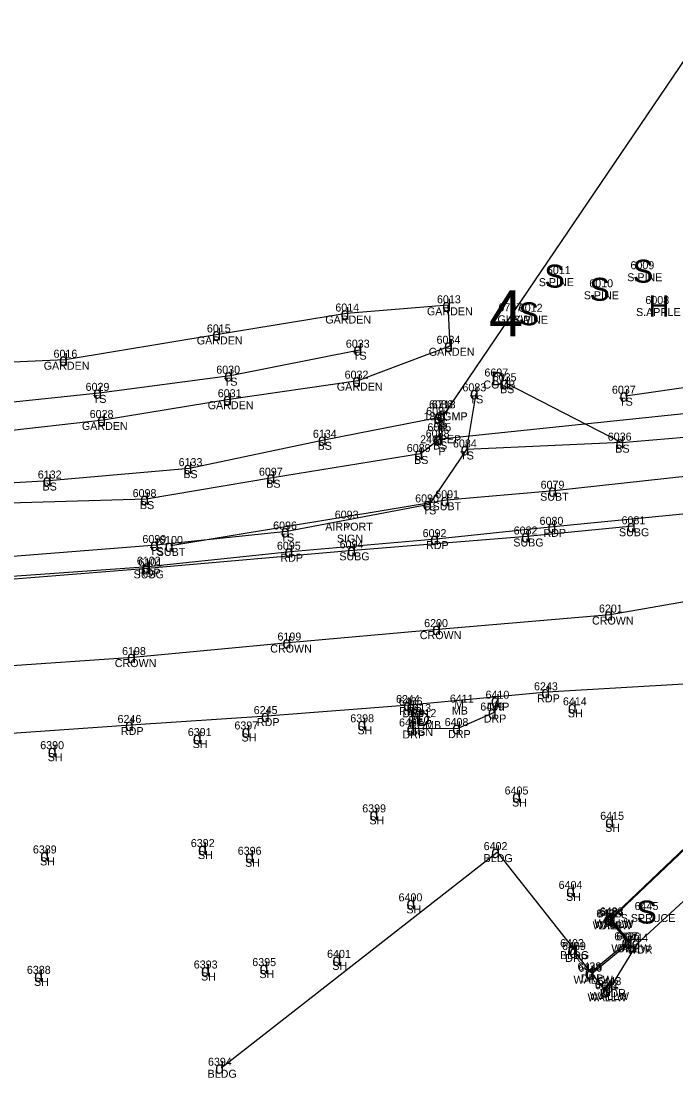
# Model space of a CAD drawing. Extents: x 69415 to 80913, y 7576 to 15059.
# Drawn here: x 75428.5 to 75592.2, y 14328.5 to 14592.6 of the extents above; entities that cross this region are included whole.
import ezdxf

# ---------------------------------------------------------------- set-up
doc = ezdxf.new("R2010")
doc.units = 0
for name, color, linetype in [('Level 11', 7, 'Continuous'), ('Level 12', 7, 'Continuous'), ('Level 13', 7, 'Continuous'), ('Level 14', 7, 'Continuous'), ('Level 15', 7, 'Continuous'), ('Level 43', 7, 'Continuous'), ('Level 46', 7, 'Continuous'), ('Level 47', 7, 'Continuous'), ('Level 48', 7, 'Continuous'), ('Level 59', 7, 'Continuous')]:
    doc.layers.add(name, color=color, linetype=linetype)

msp = doc.modelspace()

# ---------------------------------------------------------------- linework, layer by layer
at = {"layer": 'Level 11'}
for p, q in [((75607, 14470.73), (75561.56, 14466.24)), ((75561.56, 14466.24), (75532.22, 14463.17)), ((75532.22, 14463.17), (75495.79, 14460.02)), ((75495.79, 14460.02), (75460.21, 14456.27)), ((75460.21, 14456.27), (75423.86, 14453.65)), ((75595.57, 14427.04), (75560, 14424.88)), ((75560, 14424.88), (75525.49, 14421.7)), ((75525.49, 14421.7), (75489.92, 14418.94)), ((75546.65, 14419.82), (75547.4, 14422.78)), ((75489.92, 14418.94), (75455.92, 14416.71)), ((75526.32, 14421.13), (75526.33, 14415.84)), ((75537.73, 14415.94), (75546.65, 14419.82)), ((75455.92, 14416.71), (75417.43, 14413.97)), ((75526.33, 14415.84), (75537.73, 14415.94)), ((75598.04, 14389.54), (75575.57, 14368.11)), ((75575.57, 14368.11), (75580.07, 14362.41)), ((75580.07, 14362.41), (75570.88, 14354.86)), ((75570.88, 14354.86), (75567.01, 14359.97))]:
    msp.add_line(p, q, dxfattribs=at)
at = {"layer": 'Level 12'}
for p, q in [((75509.84, 14519.56), (75477.71, 14514.33)), ((75535.25, 14521.61), (75509.84, 14519.56)), ((75535.7, 14511.5), (75535.25, 14521.61)), ((75477.71, 14514.33), (75439.43, 14508.01)), ((75512.72, 14502.78), (75535.7, 14511.5)), ((75439.43, 14508.01), (75404.38, 14506.4)), ((75480.44, 14498.14), (75512.72, 14502.78)), ((75448.98, 14492.95), (75480.44, 14498.14)), ((75416.33, 14489.34), (75448.98, 14492.95)), ((75598.04, 14389.21), (75576.43, 14368.63)), ((75576.43, 14368.63), (75576.38, 14368.47)), ((75576.38, 14368.47), (75575.94, 14368.13)), ((75575.94, 14368.13), (75580.61, 14362.37)), ((75580.61, 14362.37), (75571.16, 14354.53)), ((75571.16, 14354.53), (75574.66, 14350.17)), ((75574.66, 14350.17), (75575.22, 14350.51))]:
    msp.add_line(p, q, dxfattribs=at)
at = {"layer": 'Level 13'}
for p, q in [((75478.48, 14331.04), (75547.49, 14384.94)), ((75547.49, 14384.94), (75566.61, 14360.69))]:
    msp.add_line(p, q, dxfattribs=at)
at = {"layer": 'Level 14'}
for p, q in [((75582.58, 14362.06), (75599.04, 14377.27)), ((75575.87, 14351.2), (75582.58, 14362.06))]:
    msp.add_line(p, q, dxfattribs=at)
at = {"layer": 'Level 15'}
for p, q in [((75595.97, 14478.96), (75561.74, 14475.27)), ((75561.74, 14475.27), (75534.82, 14472.89)), ((75534.82, 14472.89), (75465.87, 14461.47)), ((75581.4, 14466.39), (75554.98, 14463.83)), ((75554.98, 14463.83), (75511.48, 14460.37)), ((75511.48, 14460.37), (75460.05, 14455.87)), ((75460.05, 14455.87), (75323.23, 14444.74))]:
    msp.add_line(p, q, dxfattribs=at)
at = {"layer": 'Level 48'}
for p, q in [((75480.72, 14504.03), (75513.02, 14510.52)), ((75447.96, 14499.73), (75480.72, 14504.03)), ((75549.76, 14502.14), (75578.57, 14487.29)), ((75579.56, 14499.02), (75608.54, 14503.16)), ((75413.82, 14496.18), (75447.96, 14499.73)), ((75542.18, 14499.61), (75539.82, 14485.58)), ((75504.15, 14488), (75533.1, 14493.65)), ((75533.1, 14493.65), (75533, 14488.07)), ((75578.57, 14487.29), (75614.69, 14490.38)), ((75470.57, 14480.91), (75504.15, 14488)), ((75533, 14488.07), (75528.27, 14484.45)), ((75539.82, 14485.58), (75530.44, 14471.85)), ((75578.57, 14487.29), (75539.82, 14485.58)), ((75528.27, 14484.45), (75491.3, 14478.52)), ((75435.36, 14477.82), (75470.57, 14480.91)), ((75400.45, 14475.71), (75435.36, 14477.82)), ((75491.3, 14478.52), (75459.72, 14473.17)), ((75459.72, 14473.17), (75422.28, 14472.07)), ((75530.44, 14471.85), (75494.9, 14465.07)), ((75494.9, 14465.07), (75462.18, 14461.7)), ((75462.18, 14461.7), (75423.22, 14458.55)), ((75575.75, 14444.32), (75612.06, 14450.76)), ((75532.69, 14440.68), (75575.75, 14444.32)), ((75495.29, 14437.32), (75532.69, 14440.68)), ((75456.43, 14433.69), (75495.29, 14437.32)), ((75414.75, 14430.77), (75456.43, 14433.69))]:
    msp.add_line(p, q, dxfattribs=at)
at = {"layer": 'Level 59'}
for p, q in [((75533.87, 14493.85), (75600.89, 14592.64)), ((75687.58, 14504.22), (75533.43, 14488.13))]:
    msp.add_line(p, q, dxfattribs=at)

# ---------------------------------------------------------------- texts
at = {"layer": 'Level 12'}
msp.add_text('M', height=2.2, dxfattribs=at).set_placement((75536.74, 14420.71))
at = {"layer": 'Level 14'}
for s, height, p in [('S', 5.75, (75581.4, 14527.26)), ('S', 5.75, (75559.28, 14526.03)), ('S', 5.75, (75570.54, 14522.74)), ('S', 5.75, (75552.83, 14516.61)), ('H', 5.3, (75585.36, 14518.78)), ('S', 5.75, (75582.27, 14367.08))]:
    msp.add_text(s, height=height, dxfattribs=at).set_placement(p)
at = {"layer": 'Level 15'}
for s, height, p in [('4', 11.5, (75545.42, 14513.87)), ('D', 3.4, (75545.95, 14501.61)), ('D', 3.4, (75527.36, 14416.5))]:
    msp.add_text(s, height=height, dxfattribs=at).set_placement(p)
at = {"layer": 'Level 43'}
for p in [(75509.41, 14465.44), (75526.91, 14417.11)]:
    msp.add_text('Y', height=1.7, dxfattribs=at).set_placement(p)
at = {"layer": 'Level 46'}
for s, p in [('6009', (75580.81, 14530.63)), ('6011', (75559.9, 14529.4)), ('S.PINE', (75557.89, 14526.4)), ('6010', (75570.51, 14526.12)), ('S.PINE', (75580.01, 14527.63)), ('S.PINE', (75569.15, 14523.12)), ('6014', (75507.02, 14520.06)), ('6013', (75532.43, 14522.11)), ('6707', (75547.79, 14520.12)), ('6012', (75552.88, 14519.99)), ('6008', (75584.54, 14521.93)), ('GARDEN', (75529.92, 14519.11)), ('S.APPLE', (75582.2, 14518.93)), ('6015', (75474.9, 14514.83)), ('GARDEN', (75504.51, 14517.06)), ('GUYW', (75547.56, 14517.12)), ('S.PINE', (75551.43, 14516.99)), ('6034', (75532.32, 14512)), ('GARDEN', (75472.38, 14511.83)), ('6033', (75509.64, 14511.02)), ('6016', (75436.55, 14508.51)), ('TS', (75511.43, 14508.02)), ('GARDEN', (75530.37, 14509)), ('GARDEN', (75434.1, 14505.51)), ('6030', (75477.25, 14504.53)), ('TS', (75479.13, 14501.53)), ('6032', (75509.33, 14503.28)), ('6697', (75544.29, 14503.81)), ('6035', (75546.37, 14502.64)), ('6029', (75444.57, 14500.23)), ('GARDEN', (75507.39, 14500.28)), ('6083', (75538.79, 14500.11)), ('COMB', (75544.03, 14500.81)), ('BS', (75548.2, 14499.64)), ('6037', (75576.17, 14499.52)), ('TS', (75446.37, 14497.23)), ('6031', (75477.62, 14498.64)), ('TS', (75540.59, 14497.11)), ('TS', (75577.97, 14496.52)), ('6028', (75445.59, 14493.45)), ('GARDEN', (75475.11, 14495.64)), ('6087', (75529.72, 14494.15)), ('6086', (75530.46, 14495.88)), ('6713', (75531.13, 14495.85)), ('18CGMP', (75529.06, 14492.85)), ('18CGMP', (75529.09, 14492.88)), ('BS', (75531.54, 14491.15)), ('GARDEN', (75443.65, 14490.45)), ('6134', (75501.41, 14488.5)), ('6088', (75529.61, 14488.57)), ('6085', (75530.04, 14490.13)), ('P', (75533.25, 14489.85)), ('P', (75533.28, 14489.88)), ('BS', (75502.59, 14485.5)), ('24CPEP', (75528.22, 14487.13)), ('BS', (75531.44, 14485.57)), ('6084', (75536.43, 14486.08)), ('6036', (75575.13, 14487.79)), ('6089', (75524.88, 14484.95)), ('P', (75532.8, 14484.13)), ('TS', (75538.23, 14483.08)), ('BS', (75577.01, 14484.79)), ('6133', (75467.83, 14481.41)), ('BS', (75526.71, 14481.95)), ('6132', (75432.62, 14478.32)), ('BS', (75469.01, 14478.41)), ('6097', (75487.91, 14479.02)), ('BS', (75433.8, 14475.32)), ('BS', (75489.74, 14476.02)), ('6079', (75558.34, 14475.77)), ('6098', (75456.33, 14473.67)), ('6090', (75526.97, 14472.35)), ('6091', (75532, 14473.39)), ('SUBT', (75558.23, 14472.77)), ('BS', (75458.16, 14470.67)), ('SUBT', (75531.32, 14470.39)), ('6093', (75506.87, 14468.29)), ('TS', (75528.85, 14469.35)), ('6096', (75491.46, 14465.57)), ('AIRPORT', (75504.49, 14465.29)), ('6082', (75551.6, 14464.33)), ('6080', (75558.08, 14466.74)), ('6081', (75578.58, 14466.89)), ('6099', (75458.78, 14462.2)), ('6100', (75462.96, 14461.97)), ('TS', (75493.31, 14462.57)), ('SIGN', (75507.41, 14462.29)), ('6092', (75528.84, 14463.67)), ('RDP', (75559.05, 14463.74)), ('SUBG', (75577.93, 14463.89)), ('TS', (75460.58, 14459.2)), ('6095', (75492.41, 14460.52)), ('6094', (75508.09, 14460.87)), ('RDP', (75529.71, 14460.67)), ('SUBG', (75551.51, 14461.33)), ('6102', (75457.39, 14456.77)), ('SUBT', (75462.37, 14458.97)), ('RDP', (75493.28, 14457.52)), ('SUBG', (75508.01, 14457.87)), ('6101', (75457.79, 14456.37)), ('SUBG', (75456.57, 14453.37)), ('RDP', (75457.7, 14453.77)), ('6201', (75572.93, 14444.82)), ('6200', (75529.22, 14441.18)), ('CROWN', (75571.19, 14441.82)), ('CROWN', (75528.13, 14438.18)), ('6199', (75492.55, 14437.82)), ('6198', (75453.69, 14434.19)), ('CROWN', (75490.74, 14434.82)), ('CROWN', (75451.87, 14431.19)), ('6243', (75556.69, 14425.38)), ('6244', (75522.18, 14422.2)), ('6411', (75535.66, 14422.31)), ('6410', (75544.57, 14423.28)), ('RDP', (75557.49, 14422.38)), ('6245', (75486.61, 14419.44)), ('6406', (75522.88, 14421.63)), ('6413', (75525.02, 14419.96)), ('6409', (75543.26, 14420.32)), ('DRP', (75544.89, 14420.28)), ('6414', (75563.92, 14421.62)), ('6246', (75452.56, 14417.21)), ('6398', (75510.75, 14417.39)), ('RDP', (75522.98, 14419.2)), ('DRP', (75523.81, 14418.63)), ('REG', (75525.3, 14416.96)), ('6412', (75526.32, 14418.7)), ('MB', (75536.14, 14419.31)), ('DRP', (75544.14, 14417.32)), ('SH', (75565.15, 14418.62)), ('RDP', (75453.41, 14414.21)), ('6397', (75481.78, 14415.59)), ('RDP', (75487.41, 14416.44)), ('SH', (75512.54, 14414.39)), ('6407', (75522.94, 14416.34)), ('COMB', (75525.45, 14415.7)), ('6408', (75534.34, 14416.44)), ('6391', (75470.13, 14413.95)), ('SH', (75483.57, 14412.59)), ('DRP', (75523.82, 14413.34)), ('SIGN', (75524.92, 14413.96)), ('DRP', (75535.22, 14413.44)), ('6390', (75433.23, 14410.67)), ('SH', (75471.36, 14410.95)), ('SH', (75435.11, 14407.67)), ('6405', (75549.34, 14399.34)), ('SH', (75551.21, 14396.34)), ('6399', (75513.74, 14394.87)), ('6415', (75573.25, 14393.01)), ('SH', (75515.54, 14391.87)), ('SH', (75574.48, 14390.01)), ('6392', (75470.88, 14386.2)), ('6402', (75544.1, 14385.44)), ('6389', (75431.39, 14384.61)), ('SH', (75472.67, 14383.2)), ('6396', (75482.61, 14384.27)), ('BLDG', (75544.08, 14382.44)), ('SH', (75433.19, 14381.61)), ('SH', (75484.46, 14381.27)), ('6404', (75562.84, 14375.75)), ('6400', (75522.82, 14372.63)), ('SH', (75564.71, 14372.75)), ('SH', (75524.78, 14369.63)), ('6445', (75581.84, 14370.46)), ('6432', (75572.26, 14368.61)), ('6435', (75572.64, 14368.63)), ('6434', (75573.07, 14368.97)), ('6433', (75573.13, 14369.13)), ('S.SPRUCE', (75578.36, 14367.46)), ('WALLW', (75571.36, 14365.63)), ('WALLW', (75571.8, 14365.97)), ('WALLW', (75571.85, 14366.13)), ('DRP', (75573.05, 14365.61)), ('6437', (75576.76, 14362.91)), ('6436', (75577.25, 14362.87)), ('6444', (75579.27, 14362.56)), ('6403', (75563.22, 14361.19)), ('6439', (75563.7, 14360.47)), ('WALLW', (75576.03, 14359.87)), ('DRP', (75577.56, 14359.91)), ('WDR', (75579.94, 14359.56)), ('6395', (75486.25, 14356.45)), ('6401', (75504.95, 14358.51)), ('BLDG', (75563.2, 14358.19)), ('DRP', (75564.5, 14357.47)), ('6388', (75429.89, 14354.51)), ('6393', (75471.62, 14355.85)), ('SH', (75488.04, 14353.45)), ('SH', (75506.25, 14355.51)), ('6438', (75567.57, 14355.36)), ('6440', (75567.77, 14355.03)), ('SH', (75431.68, 14351.51)), ('SH', (75473.42, 14352.85)), ('WALLW', (75566.58, 14352.03)), ('DRP', (75568.37, 14352.36)), ('6442', (75571.91, 14351.01)), ('6443', (75572.57, 14351.7)), ('6441', (75571.92, 14350.67)), ('WDR', (75573.24, 14348.7)), ('WALLW', (75570.08, 14347.67)), ('WALLW', (75570.64, 14348.01)), ('6394', (75475.17, 14331.54)), ('BLDG', (75475.07, 14328.54))]:
    msp.add_text(s, height=2, dxfattribs=at).set_placement(p)
at = {"layer": 'Level 47'}
for p in [(75533.75, 14520.11), (75508.34, 14518.06), (75476.21, 14512.83), (75511.52, 14509.02), (75534.2, 14510), (75437.93, 14506.51), (75479.22, 14502.53), (75511.22, 14501.28), (75548.26, 14500.64), (75446.46, 14498.23), (75540.68, 14498.11), (75478.94, 14496.64), (75578.06, 14497.52), (75532.37, 14492.35), (75532.4, 14492.38), (75447.48, 14491.45), (75531.6, 14492.15), (75502.65, 14486.5), (75531.5, 14486.57), (75531.93, 14486.63), (75577.07, 14485.79), (75526.77, 14482.95), (75538.32, 14484.08), (75469.07, 14479.41), (75489.8, 14477.02), (75433.86, 14476.32), (75560.24, 14473.77), (75458.22, 14471.67), (75533.32, 14471.39), (75528.94, 14470.35), (75493.4, 14463.57), (75560.06, 14464.74), (75579.9, 14464.89), (75530.72, 14461.67), (75553.48, 14462.33), (75460.68, 14460.2), (75464.37, 14459.97), (75494.29, 14458.52), (75509.98, 14458.87), (75458.55, 14454.37), (75458.71, 14454.77), (75574.25, 14442.82), (75531.19, 14439.18), (75493.79, 14435.82), (75454.93, 14432.19), (75545.9, 14421.28), (75558.5, 14423.38), (75523.99, 14420.2), (75524.82, 14419.63), (75545.15, 14418.32), (75565.16, 14419.62), (75488.42, 14417.44), (75454.42, 14415.21), (75483.59, 14413.59), (75512.55, 14415.39), (75524.83, 14414.34), (75536.23, 14414.44), (75471.37, 14411.95), (75435.12, 14408.67), (75551.22, 14397.34), (75515.55, 14392.87), (75574.49, 14391.01), (75472.69, 14384.2), (75433.21, 14382.61), (75484.47, 14382.27), (75545.99, 14383.44), (75564.73, 14373.75), (75524.79, 14370.63), (75574.07, 14366.61), (75574.44, 14366.63), (75574.88, 14366.97), (75574.93, 14367.13), (75578.57, 14360.91), (75579.11, 14360.87), (75581.08, 14360.56), (75565.11, 14359.19), (75565.51, 14358.47), (75506.27, 14356.51), (75431.7, 14352.51), (75473.43, 14353.85), (75488.06, 14354.45), (75569.38, 14353.36), (75569.66, 14353.03), (75574.37, 14349.7), (75573.16, 14348.67), (75573.72, 14349.01), (75476.98, 14329.54)]:
    msp.add_text('d', height=3, dxfattribs=at).set_placement(p)

doc.saveas('drawing.dxf')
